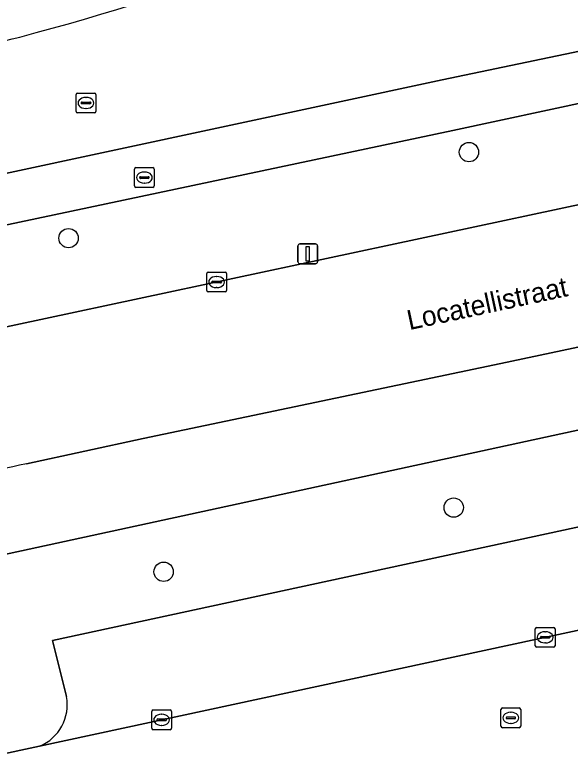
# Model space of a CAD drawing. Extents: x 159053 to 160042, y 380449 to 381423.
# Drawn here: x 159337.21 to 159365.32, y 380753.65 to 380790.65 of the extents above; entities that cross this region are included whole.
import ezdxf

# ---------------------------------------------------------------- set-up
doc = ezdxf.new("R2010")
doc.units = 0
for name, color, linetype in [('IMGEO_Berm_groen', 7, 'Continuous'), ('IMGEO_Boom', 7, 'Continuous'), ('IMGEO_Fietspad_gesloten', 7, 'Continuous'), ('IMGEO_Groenvoorziening', 7, 'Continuous'), ('IMGEO_Kolk', 7, 'Continuous'), ('IMGEO_Lichtmast', 7, 'Continuous'), ('IMGEO_Openbare_ruimte_label', 7, 'Continuous'), ('IMGEO_Parkeervlak_open', 7, 'Continuous'), ('IMGEO_Rijbaan_lokaal_gesloten', 7, 'Continuous'), ('IMGEO_Rijbaan_lokaal_open', 7, 'Continuous'), ('IMGEO_Rioolput', 7, 'Continuous'), ('IMGEO_Waterloop', 7, 'Continuous')]:
    doc.layers.add(name, color=color, linetype=linetype)

msp = doc.modelspace()

# ---------------------------------------------------------------- linework, layer by layer
at = {"layer": 'IMGEO_Berm_groen'}
for points in [[(159430.434, 380783.675), (159489.591, 380796.5), (159488.721, 380800.291), (159449.035, 380791.688), (159397.83, 380780.651), (159361.803, 380773.018), (159343.706, 380769.224), (159337.802, 380767.938)], [(159488.772, 380785.988), (159491.921, 380786.667), (159489.591, 380796.5), (159430.434, 380783.675), (159313.594, 380758.346), (159311.805, 380757.958), (159312.551, 380755.107), (159314.223, 380750), (159314.651, 380748.545), (159321.417, 380750), (159338.469, 380753.667)], [(159339.127, 380759.013), (159403.077, 380772.816), (159440.703, 380780.86), (159485.805, 380790.618), (159486.43, 380787.573)], [(159313.854, 380760.345), (159311.331, 380759.772), (159311.805, 380757.958), (159313.594, 380758.346), (159430.434, 380783.675)], [(159339.833, 380756.176), (159339.127, 380759.013)]]:
    msp.add_lwpolyline(points, dxfattribs=at)
msp.add_lwpolyline([(159357.725, 380779.326), (159367.51, 380781.42), (159366.443, 380786.308), (159359.379, 380784.797), (159327.794, 380778.122), (159307.608, 380773.752), (159308.839, 380768.865), (159329.278, 380773.264)], close=True, dxfattribs=at)
for centre, radius, start, end in [((159349.55, 380710.171), 58.949, 101.4956, 112.28893), ((159337.622, 380755.753), 2.251, 292.1041, 10.8351)]:
    msp.add_arc(centre, radius, start, end, dxfattribs=at)
at = {"layer": 'IMGEO_Boom'}
for centre in [(159360.188, 380783.701), (159339.935, 380779.351), (159359.416, 380765.727), (159344.746, 380762.481)]:
    msp.add_circle(centre, 0.489, dxfattribs=at)
at = {"layer": 'IMGEO_Fietspad_gesloten'}
for points in [[(159303.62, 380772.914), (159307.608, 380773.752), (159327.794, 380778.122), (159359.379, 380784.797), (159366.443, 380786.308), (159395.428, 380792.508), (159424.344, 380798.667), (159454.834, 380805.321)], [(159392.3, 380794.485), (159373.348, 380790.451), (159366.188, 380788.885), (159358.839, 380787.353), (159325.335, 380780.169), (159309.38, 380776.666), (159305.196, 380775.715), (159298.664, 380774.48), (159266.37, 380767.539), (159264.623, 380767.174), (159263.34, 380766.906), (159263.863, 380764.398), (159264.984, 380764.626), (159269.242, 380765.506), (159274.225, 380766.622), (159275.957, 380767.009), (159288.187, 380769.652), (159296.787, 380771.476), (159302.804, 380772.741)]]:
    msp.add_lwpolyline(points, dxfattribs=at)
at = {"layer": 'IMGEO_Groenvoorziening'}
msp.add_lwpolyline([(159325.042, 380787.471), (159323.835, 380787.372), (159324.06, 380786.292), (159325.335, 380780.169), (159358.839, 380787.353), (159366.188, 380788.885), (159373.348, 380790.451), (159392.3, 380794.485), (159401.342, 380796.428), (159399.93, 380802.675), (159400.53, 380803.747), (159401.611, 380804.823), (159402.648, 380805.353), (159456.373, 380821.858)], dxfattribs=at)
for centre, radius, start, end in [((159299.901, 380931.389), 146.758, 284.83146, 295.45751), ((159319.659, 380858.776), 71.508, 274.31721, 284.42043)]:
    msp.add_arc(centre, radius, start, end, dxfattribs=at)
at = {"layer": 'IMGEO_Kolk'}
for p, q in [((159346.999, 380777.632), (159347.851, 380777.632)), ((159346.924, 380776.706), (159346.924, 380777.558)), ((159347.412, 380777.412), (159347.437, 380777.412)), ((159347.925, 380777.558), (159347.925, 380776.706)), ((159347.183, 380777.126), (159347.183, 380777.138)), ((159347.621, 380777.089), (159347.223, 380777.089)), ((159347.226, 380777.175), (159347.624, 380777.175)), ((159347.435, 380776.852), (159347.41, 380776.852)), ((159347.667, 380777.138), (159347.667, 380777.126)), ((159347.851, 380776.632), (159346.999, 380776.632)), ((159363.542, 380758.742), (159363.542, 380759.594)), ((159363.617, 380759.668), (159364.469, 380759.668)), ((159364.543, 380759.594), (159364.543, 380758.742)), ((159363.801, 380759.162), (159363.801, 380759.174)), ((159364.239, 380759.125), (159363.841, 380759.125)), ((159363.844, 380759.211), (159364.242, 380759.211)), ((159364.03, 380759.448), (159364.055, 380759.448)), ((159364.285, 380759.174), (159364.285, 380759.162)), ((159364.053, 380758.888), (159364.028, 380758.888)), ((159364.469, 380758.668), (159363.617, 380758.668)), ((159344.144, 380754.571), (159344.144, 380755.423)), ((159344.219, 380755.497), (159345.071, 380755.497)), ((159345.145, 380755.423), (159345.145, 380754.571)), ((159344.446, 380755.04), (159344.844, 380755.04)), ((159344.632, 380755.277), (159344.657, 380755.277)), ((159344.403, 380754.991), (159344.403, 380755.003)), ((159344.841, 380754.954), (159344.443, 380754.954)), ((159344.655, 380754.717), (159344.63, 380754.717)), ((159344.887, 380755.003), (159344.887, 380754.991)), ((159345.071, 380754.497), (159344.219, 380754.497))]:
    msp.add_line(p, q, dxfattribs=at)
for points in [[(159346.999, 380777.632), (159347.851, 380777.632)], [(159346.924, 380776.706), (159346.924, 380777.558)], [(159347.925, 380777.558), (159347.925, 380776.706)], [(159347.851, 380776.632), (159346.999, 380776.632)], [(159363.542, 380758.742), (159363.542, 380759.594)], [(159363.617, 380759.668), (159364.469, 380759.668)], [(159364.543, 380759.594), (159364.543, 380758.742)], [(159364.469, 380758.668), (159363.617, 380758.668)], [(159344.144, 380754.571), (159344.144, 380755.423)], [(159344.219, 380755.497), (159345.071, 380755.497)], [(159345.145, 380755.423), (159345.145, 380754.571)], [(159345.071, 380754.497), (159344.219, 380754.497)]]:
    msp.add_lwpolyline(points, dxfattribs=at)
for centre, radius, start, end in [((159347.001, 380777.556), 0.0765, 91.552, 178.448), ((159347.001, 380777.556), 0.0765, 91.552, 178.448), ((159347.849, 380777.556), 0.0765, 1.552, 88.448), ((159347.849, 380777.556), 0.0765, 1.552, 88.448), ((159347.223, 380777.135), 0.0403, 85.8775, 175.7526), ((159347.22, 380777.125), 0.0366, 178.938, 274.7102), ((159347.624, 380777.132), 0.043, 264.8664, 352.4533), ((159347.628, 380777.137), 0.0386, 1.7309, 96.639), ((159347.001, 380776.708), 0.0765, 181.552, 268.448), ((159347.001, 380776.708), 0.0765, 181.552, 268.448), ((159347.849, 380776.708), 0.0765, 271.552, 358.448), ((159347.849, 380776.708), 0.0765, 271.552, 358.448), ((159363.619, 380759.592), 0.0765, 91.552, 178.448), ((159363.619, 380759.592), 0.0765, 91.552, 178.448), ((159364.467, 380759.592), 0.0765, 1.552, 88.448), ((159364.467, 380759.592), 0.0765, 1.552, 88.448), ((159363.841, 380759.171), 0.0403, 85.8775, 175.7526), ((159363.838, 380759.161), 0.0366, 178.938, 274.7102), ((159364.242, 380759.168), 0.043, 264.8664, 352.4533), ((159364.246, 380759.173), 0.0386, 1.7309, 96.639), ((159363.619, 380758.744), 0.0765, 181.552, 268.448), ((159363.619, 380758.744), 0.0765, 181.552, 268.448), ((159364.467, 380758.744), 0.0765, 271.552, 358.448), ((159364.467, 380758.744), 0.0765, 271.552, 358.448), ((159344.221, 380755.421), 0.0765, 91.552, 178.448), ((159344.221, 380755.421), 0.0765, 91.552, 178.448), ((159345.069, 380755.421), 0.0765, 1.552, 88.448), ((159345.069, 380755.421), 0.0765, 1.552, 88.448), ((159344.443, 380755), 0.0403, 85.8775, 175.7526), ((159344.848, 380755.002), 0.0386, 1.7309, 96.639), ((159344.44, 380754.99), 0.0366, 178.938, 274.7102), ((159344.844, 380754.997), 0.043, 264.8664, 352.4533), ((159344.221, 380754.573), 0.0765, 181.552, 268.448), ((159344.221, 380754.573), 0.0765, 181.552, 268.448), ((159345.069, 380754.573), 0.0765, 271.552, 358.448), ((159345.069, 380754.573), 0.0765, 271.552, 358.448)]:
    msp.add_arc(centre, radius, start, end, dxfattribs=at)
for centre, major_axis, ratio, start_param, end_param in [((159347.411, 380777.132), (-0.387, 0.002), 0.722429, 4.712389, 7.853982), ((159347.436, 380777.132), (-0.39, 0.002), 0.717154, 1.570796, 4.712389), ((159364.029, 380759.168), (-0.387, 0.002), 0.722429, 4.712389, 7.853982), ((159364.054, 380759.168), (-0.39, 0.002), 0.717154, 1.570796, 4.712389), ((159344.631, 380754.997), (-0.387, 0.002), 0.722429, 4.712389, 7.853982), ((159344.656, 380754.997), (-0.39, 0.002), 0.717154, 1.570796, 4.712389)]:
    msp.add_ellipse(centre, major_axis=major_axis, ratio=ratio, start_param=start_param, end_param=end_param, dxfattribs=at)
at = {"layer": 'IMGEO_Lichtmast'}
for p, q in [((159351.538, 380778.157), (159351.538, 380778.957)), ((159351.538, 380778.957), (159351.538, 380778.157)), ((159351.638, 380779.057), (159352.428, 380779.057)), ((159352.428, 380779.057), (159351.638, 380779.057)), ((159352.528, 380778.957), (159352.528, 380778.157)), ((159352.528, 380778.157), (159352.528, 380778.957)), ((159352.428, 380778.057), (159351.638, 380778.057)), ((159351.638, 380778.057), (159352.428, 380778.057))]:
    msp.add_line(p, q, dxfattribs=at)
msp.add_lwpolyline([(159351.958, 380778.932), (159352.108, 380778.932), (159352.108, 380778.182), (159351.958, 380778.182), (159351.958, 380778.932)], dxfattribs=at)
for centre, start, end in [((159351.638, 380778.957), 90, 180), ((159351.638, 380778.957), 90, 180), ((159352.428, 380778.957), 0, 90), ((159352.428, 380778.957), 360, 90), ((159351.638, 380778.157), 180, 270), ((159351.638, 380778.157), 180, 270), ((159352.428, 380778.157), 270, 0), ((159352.428, 380778.157), 270, 0)]:
    msp.add_arc(centre, 0.1, start, end, dxfattribs=at)
at = {"layer": 'IMGEO_Parkeervlak_open'}
for points in [[(159486.43, 380787.573), (159485.805, 380790.618), (159440.703, 380780.86), (159403.077, 380772.816), (159339.127, 380759.013), (159339.833, 380756.176)], [(159338.469, 380753.667), (159488.772, 380785.988)]]:
    msp.add_lwpolyline(points, dxfattribs=at)
msp.add_arc((159337.622, 380755.753), 2.251, 292.1041, 10.8351, dxfattribs=at)
at = {"layer": 'IMGEO_Rijbaan_lokaal_gesloten'}
for points in [[(159425.879, 380793.969), (159406.898, 380789.823), (159386.584, 380785.503), (159367.51, 380781.42), (159357.725, 380779.326), (159329.278, 380773.264), (159308.839, 380768.865), (159305.028, 380768.087), (159303.915, 380767.859), (159300.915, 380767.321), (159273.958, 380761.512)], [(159337.802, 380767.938), (159343.706, 380769.224), (159361.803, 380773.018), (159397.83, 380780.651)]]:
    msp.add_lwpolyline(points, dxfattribs=at)
msp.add_arc((159349.55, 380710.171), 58.949, 101.4956, 112.28893, dxfattribs=at)
at = {"layer": 'IMGEO_Rijbaan_lokaal_open'}
msp.add_lwpolyline([(159505.169, 380786.318), (159501.193, 380790.047), (159500, 380788.832), (159499.612, 380788.437), (159499.362, 380788.373), (159498.184, 380788.12), (159497.714, 380788.011), (159493.697, 380787.079), (159491.921, 380786.667), (159488.772, 380785.988), (159338.469, 380753.667), (159321.417, 380750), (159314.651, 380748.545), (159310.102, 380747.567), (159309.975, 380747.54), (159304.264, 380746.312), (159303.103, 380746.062)], dxfattribs=at)
at = {"layer": 'IMGEO_Rioolput'}
for p, q in [((159340.317, 380785.76), (159340.317, 380786.612)), ((159340.392, 380786.686), (159341.244, 380786.686)), ((159341.318, 380786.612), (159341.318, 380785.76)), ((159340.576, 380786.18), (159340.576, 380786.192)), ((159341.014, 380786.143), (159340.616, 380786.143)), ((159340.619, 380786.229), (159341.017, 380786.229)), ((159340.805, 380786.466), (159340.83, 380786.466)), ((159341.06, 380786.192), (159341.06, 380786.18)), ((159340.828, 380785.906), (159340.803, 380785.906)), ((159341.244, 380785.686), (159340.392, 380785.686)), ((159343.271, 380781.99), (159343.271, 380782.842)), ((159343.346, 380782.916), (159344.198, 380782.916)), ((159344.272, 380782.842), (159344.272, 380781.99)), ((159343.53, 380782.41), (159343.53, 380782.422)), ((159343.573, 380782.459), (159343.971, 380782.459)), ((159343.759, 380782.696), (159343.784, 380782.696)), ((159344.014, 380782.422), (159344.014, 380782.41)), ((159343.968, 380782.373), (159343.57, 380782.373)), ((159343.782, 380782.136), (159343.757, 380782.136)), ((159344.198, 380781.916), (159343.346, 380781.916)), ((159361.807, 380754.671), (159361.807, 380755.523)), ((159361.882, 380755.597), (159362.734, 380755.597)), ((159362.808, 380755.523), (159362.808, 380754.671)), ((159362.066, 380755.091), (159362.066, 380755.103)), ((159362.504, 380755.054), (159362.106, 380755.054)), ((159362.109, 380755.14), (159362.507, 380755.14)), ((159362.295, 380755.377), (159362.32, 380755.377)), ((159362.55, 380755.103), (159362.55, 380755.091)), ((159362.318, 380754.817), (159362.293, 380754.817)), ((159362.734, 380754.597), (159361.882, 380754.597))]:
    msp.add_line(p, q, dxfattribs=at)
for points in [[(159340.317, 380785.76), (159340.317, 380786.612)], [(159340.392, 380786.686), (159341.244, 380786.686)], [(159341.318, 380786.612), (159341.318, 380785.76)], [(159341.244, 380785.686), (159340.392, 380785.686)], [(159343.271, 380781.99), (159343.271, 380782.842)], [(159343.346, 380782.916), (159344.198, 380782.916)], [(159344.272, 380782.842), (159344.272, 380781.99)], [(159344.198, 380781.916), (159343.346, 380781.916)], [(159361.807, 380754.671), (159361.807, 380755.523)], [(159361.882, 380755.597), (159362.734, 380755.597)], [(159362.808, 380755.523), (159362.808, 380754.671)], [(159362.734, 380754.597), (159361.882, 380754.597)]]:
    msp.add_lwpolyline(points, dxfattribs=at)
for centre, radius, start, end in [((159340.394, 380786.61), 0.0765, 91.552, 178.448), ((159340.394, 380786.61), 0.0765, 91.552, 178.448), ((159341.242, 380786.61), 0.0765, 1.552, 88.448), ((159341.242, 380786.61), 0.0765, 1.552, 88.448), ((159340.616, 380786.189), 0.0403, 85.8775, 175.7526), ((159340.613, 380786.179), 0.0366, 178.938, 274.7102), ((159341.017, 380786.186), 0.043, 264.8664, 352.4533), ((159341.021, 380786.191), 0.0386, 1.7309, 96.639), ((159340.394, 380785.762), 0.0765, 181.552, 268.448), ((159340.394, 380785.762), 0.0765, 181.552, 268.448), ((159341.242, 380785.762), 0.0765, 271.552, 358.448), ((159341.242, 380785.762), 0.0765, 271.552, 358.448), ((159343.348, 380782.84), 0.0765, 91.552, 178.448), ((159343.348, 380782.84), 0.0765, 91.552, 178.448), ((159344.196, 380782.84), 0.0765, 1.552, 88.448), ((159344.196, 380782.84), 0.0765, 1.552, 88.448), ((159343.57, 380782.419), 0.0403, 85.8775, 175.7526), ((159343.567, 380782.409), 0.0366, 178.938, 274.7102), ((159343.971, 380782.416), 0.043, 264.8664, 352.4533), ((159343.975, 380782.421), 0.0386, 1.7309, 96.639), ((159343.348, 380781.992), 0.0765, 181.552, 268.448), ((159343.348, 380781.992), 0.0765, 181.552, 268.448), ((159344.196, 380781.992), 0.0765, 271.552, 358.448), ((159344.196, 380781.992), 0.0765, 271.552, 358.448), ((159361.884, 380755.521), 0.0765, 91.552, 178.448), ((159361.884, 380755.521), 0.0765, 91.552, 178.448), ((159362.732, 380755.521), 0.0765, 1.552, 88.448), ((159362.732, 380755.521), 0.0765, 1.552, 88.448), ((159362.106, 380755.1), 0.0403, 85.8775, 175.7526), ((159362.103, 380755.09), 0.0366, 178.938, 274.7102), ((159362.507, 380755.097), 0.043, 264.8664, 352.4533), ((159362.511, 380755.102), 0.0386, 1.7309, 96.639), ((159361.884, 380754.673), 0.0765, 181.552, 268.448), ((159361.884, 380754.673), 0.0765, 181.552, 268.448), ((159362.732, 380754.673), 0.0765, 271.552, 358.448), ((159362.732, 380754.673), 0.0765, 271.552, 358.448)]:
    msp.add_arc(centre, radius, start, end, dxfattribs=at)
for centre, major_axis, ratio, start_param, end_param in [((159340.804, 380786.186), (-0.387, 0.002), 0.722429, 4.712389, 7.853982), ((159340.829, 380786.186), (-0.39, 0.002), 0.717154, 1.570796, 4.712389), ((159343.758, 380782.416), (-0.387, 0.002), 0.722429, 4.712389, 7.853982), ((159343.783, 380782.416), (-0.39, 0.002), 0.717154, 1.570796, 4.712389), ((159362.294, 380755.097), (-0.387, 0.002), 0.722429, 4.712389, 7.853982), ((159362.319, 380755.097), (-0.39, 0.002), 0.717154, 1.570796, 4.712389)]:
    msp.add_ellipse(centre, major_axis=major_axis, ratio=ratio, start_param=start_param, end_param=end_param, dxfattribs=at)
at = {"layer": 'IMGEO_Waterloop'}
for centre, radius, start, end in [((159299.901, 380931.389), 146.758, 284.83146, 295.45751), ((159319.659, 380858.776), 71.508, 274.31721, 284.42043)]:
    msp.add_arc(centre, radius, start, end, dxfattribs=at)

# ---------------------------------------------------------------- texts
at = {"layer": 'IMGEO_Openbare_ruimte_label'}
msp.add_text('Locatellistraat', height=1, rotation=12.1188, dxfattribs=at).set_placement((159357.174, 380774.699))

doc.saveas('drawing.dxf')
